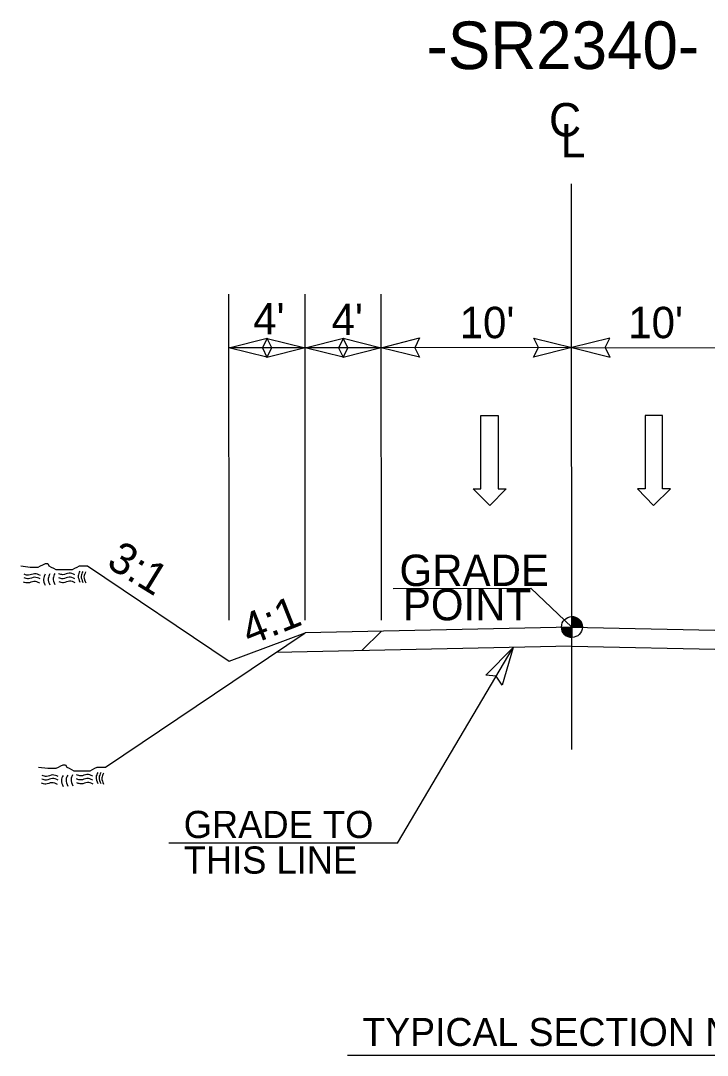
# Model space of a CAD drawing. Extents: x 2241081 to 2251104, y 658534 to 663427.
# Drawn here: x 2241729 to 2241909.2, y 660188.5 to 660460.2 of the extents above; entities that cross this region are included whole.
import ezdxf

# ---------------------------------------------------------------- set-up
doc = ezdxf.new("R2010")
doc.units = 0
for name, color, linetype in [('Old_Level_1', 7, 'Continuous'), ('Old_Level_11', 7, 'Continuous'), ('Old_Level_2', 7, 'Continuous'), ('Old_Level_3', 7, 'Continuous'), ('Prop Dimension Text', 7, 'Continuous'), ('Prop Lane Arrow CELL', 7, 'Continuous'), ('Typical Grade Point Symbol CELL', 7, 'Continuous'), ('Typical Hinge Slope Interstate CELL', 7, 'Continuous'), ('Typical Terminator CELL', 7, 'Continuous'), ('Typical Text Centerline CELL', 7, 'Continuous'), ('Typical Text Grade Point CELL', 7, 'Continuous'), ('Typical Text Label CELL', 7, 'Continuous')]:
    doc.layers.add(name, color=color, linetype=linetype)

# ---------------------------------------------------------------- blocks, each defined once
blk = doc.blocks.new('TERMINATOR')
at = {"layer": 'Typical Terminator CELL'}
blk.add_lwpolyline([(-0.4687, 0.0807), (0, 0), (-0.4713, -0.0833), (-0.4114, 0)], close=True, dxfattribs=at)

msp = doc.modelspace()

# ---------------------------------------------------------------- linework, layer by layer
at = {"layer": 'Old_Level_1'}
for p, q in [((2241746.53, 660316.99), (2241783.69, 660291.99)), ((2241751.23, 660264.14), (2241803.68, 660299.45)), ((2241783.69, 660291.99), (2241803.68, 660299.45))]:
    msp.add_line(p, q, dxfattribs=at)
for points in [[(2241728.97, 660316.99), (2241731.43, 660316.69), (2241732.05, 660316.69), (2241732.98, 660316.69), (2241733.59, 660316.69), (2241734.21, 660316.99), (2241734.82, 660317.3), (2241735.44, 660317.61), (2241736.06, 660317.61), (2241736.37, 660316.99), (2241736.98, 660316.69), (2241737.6, 660316.38), (2241738.21, 660316.07), (2241738.83, 660316.07), (2241739.45, 660316.07), (2241740.06, 660316.07), (2241740.68, 660316.07), (2241741.29, 660316.07), (2241741.91, 660316.07), (2241742.53, 660316.07), (2241743.14, 660316.38), (2241743.76, 660316.69), (2241744.37, 660316.99), (2241745.3, 660316.99), (2241745.92, 660316.99), (2241746.53, 660316.99)], [(2241733.67, 660264.14), (2241736.13, 660263.84), (2241736.75, 660263.84), (2241737.67, 660263.84), (2241738.29, 660263.84), (2241738.9, 660264.14), (2241739.52, 660264.45), (2241740.14, 660264.76), (2241740.75, 660264.76), (2241741.06, 660264.14), (2241741.68, 660263.84), (2241742.3, 660263.53), (2241742.91, 660263.22), (2241743.53, 660263.22), (2241744.14, 660263.22), (2241744.76, 660263.22), (2241745.38, 660263.22), (2241745.99, 660263.22), (2241746.61, 660263.22), (2241747.22, 660263.22), (2241747.84, 660263.53), (2241748.46, 660263.84), (2241749.07, 660264.14), (2241750, 660264.14), (2241750.61, 660264.14), (2241751.23, 660264.14)]]:
    msp.add_lwpolyline(points, dxfattribs=at)
at = {"layer": 'Old_Level_11'}
msp.add_line((2241827.86, 660244.22), (2241858.28, 660295.6), dxfattribs=at)
at = {"layer": 'Old_Level_2'}
for p, q in [((2241873.68, 660300.94), (2241803.68, 660299.45)), ((2241873.59, 660300.94), (2241943.59, 660299.45)), ((2241823.68, 660299.87), (2241818.57, 660294.76)), ((2241873.58, 660295.94), (2241796.01, 660294.28)), ((2241873.69, 660295.94), (2241951.27, 660294.28))]:
    msp.add_line(p, q, dxfattribs=at)
for points in [[(2241734.1, 660313.57), (2241732.6, 660314.01), (2241731.01, 660313.6), (2241729.86, 660313.85)], [(2241734.1, 660313.57), (2241732.6, 660314.01), (2241731.01, 660313.6), (2241729.86, 660313.85)], [(2241734.14, 660314.52), (2241732.63, 660314.95), (2241731.05, 660314.54), (2241729.9, 660314.79)], [(2241734.14, 660314.52), (2241732.63, 660314.95), (2241731.05, 660314.54), (2241729.9, 660314.79)], [(2241735.39, 660314.8), (2241734.96, 660313.56), (2241735.42, 660311.92)], [(2241735.39, 660314.8), (2241734.96, 660313.56), (2241735.42, 660311.92)], [(2241736.6, 660314.91), (2241736.18, 660313.67), (2241736.63, 660312.02)], [(2241736.6, 660314.91), (2241736.18, 660313.67), (2241736.63, 660312.02)], [(2241737.91, 660315.01), (2241737.49, 660313.77), (2241737.94, 660312.13)], [(2241737.91, 660315.01), (2241737.49, 660313.77), (2241737.94, 660312.13)], [(2241743.17, 660314.66), (2241741.67, 660315.09), (2241740.07, 660314.69), (2241738.93, 660314.94)], [(2241743.17, 660314.66), (2241741.67, 660315.09), (2241740.07, 660314.69), (2241738.93, 660314.94)], [(2241743.18, 660313.61), (2241741.67, 660314.04), (2241740.09, 660313.63), (2241738.94, 660313.89)], [(2241743.18, 660313.61), (2241741.67, 660314.04), (2241740.09, 660313.63), (2241738.94, 660313.89)], [(2241744.5, 660315.63), (2241744.07, 660314.38), (2241744.53, 660312.74)], [(2241744.5, 660315.63), (2241744.07, 660314.38), (2241744.53, 660312.74)], [(2241745.28, 660315.55), (2241744.86, 660314.3), (2241745.32, 660312.65)], [(2241745.28, 660315.55), (2241744.86, 660314.3), (2241745.32, 660312.65)], [(2241746.01, 660315.4), (2241745.58, 660314.16), (2241746.04, 660312.52)], [(2241746.01, 660315.4), (2241745.58, 660314.16), (2241746.04, 660312.52)], [(2241733.95, 660312.48), (2241732.45, 660312.91), (2241730.85, 660312.51), (2241729.71, 660312.76)], [(2241743.3, 660312.56), (2241741.79, 660312.98), (2241740.2, 660312.58), (2241739.05, 660312.84)], [(2241743.3, 660312.56), (2241741.79, 660312.98), (2241740.2, 660312.58), (2241739.05, 660312.84)], [(2241738.84, 660261.67), (2241737.33, 660262.1), (2241735.75, 660261.69), (2241734.6, 660261.95)], [(2241738.84, 660261.67), (2241737.33, 660262.1), (2241735.75, 660261.69), (2241734.6, 660261.95)], [(2241740.08, 660261.96), (2241739.66, 660260.71), (2241740.12, 660259.07)], [(2241740.08, 660261.96), (2241739.66, 660260.71), (2241740.12, 660259.07)], [(2241741.3, 660262.07), (2241740.87, 660260.82), (2241741.33, 660259.17)], [(2241741.3, 660262.07), (2241740.87, 660260.82), (2241741.33, 660259.17)], [(2241742.61, 660262.17), (2241742.19, 660260.93), (2241742.64, 660259.28)], [(2241742.61, 660262.17), (2241742.19, 660260.93), (2241742.64, 660259.28)], [(2241747.87, 660261.81), (2241746.37, 660262.24), (2241744.77, 660261.84), (2241743.63, 660262.1)], [(2241747.87, 660261.81), (2241746.37, 660262.24), (2241744.77, 660261.84), (2241743.63, 660262.1)], [(2241749.2, 660262.78), (2241748.77, 660261.54), (2241749.23, 660259.89)], [(2241749.2, 660262.78), (2241748.77, 660261.54), (2241749.23, 660259.89)], [(2241749.97, 660262.7), (2241749.56, 660261.45), (2241750.01, 660259.81)], [(2241749.97, 660262.7), (2241749.56, 660261.45), (2241750.01, 660259.81)], [(2241750.71, 660262.56), (2241750.28, 660261.32), (2241750.74, 660259.67)], [(2241750.71, 660262.56), (2241750.28, 660261.32), (2241750.74, 660259.67)], [(2241738.65, 660259.63), (2241737.14, 660260.06), (2241735.55, 660259.66), (2241734.41, 660259.92)], [(2241738.8, 660260.72), (2241737.29, 660261.16), (2241735.71, 660260.75), (2241734.56, 660261.01)], [(2241738.8, 660260.72), (2241737.29, 660261.16), (2241735.71, 660260.75), (2241734.56, 660261.01)], [(2241747.88, 660260.77), (2241746.37, 660261.19), (2241744.79, 660260.78), (2241743.64, 660261.04)], [(2241747.88, 660260.77), (2241746.37, 660261.19), (2241744.79, 660260.78), (2241743.64, 660261.04)], [(2241747.99, 660259.71), (2241746.49, 660260.13), (2241744.89, 660259.74), (2241743.75, 660259.99)], [(2241747.99, 660259.71), (2241746.49, 660260.13), (2241744.89, 660259.74), (2241743.75, 660259.99)]]:
    msp.add_spline(points, degree=3, dxfattribs=at)
at = {"layer": 'Prop Dimension Text'}
for p, q in [((2241783.68, 660302.76), (2241783.63, 660388.35)), ((2241803.68, 660302.77), (2241803.63, 660388.36)), ((2241823.68, 660302.79), (2241823.63, 660388.38)), ((2241803.64, 660374.29), (2241783.64, 660374.28)), ((2241823.64, 660374.31), (2241803.64, 660374.29)), ((2241873.64, 660374.34), (2241823.64, 660374.31)), ((2241873.64, 660374.34), (2241923.64, 660374.31)), ((2241827.86, 660244.22), (2241767.86, 660244.18))]:
    msp.add_line(p, q, dxfattribs=at)
at = {"layer": 'Prop Lane Arrow CELL'}
for p, q in [((2241849.78, 660356.49), (2241854.33, 660356.5)), ((2241849.8, 660337.2), (2241849.78, 660356.49)), ((2241854.33, 660356.5), (2241854.34, 660337.2)), ((2241892.94, 660356.5), (2241892.93, 660337.2)), ((2241897.49, 660356.49), (2241892.94, 660356.5)), ((2241897.48, 660337.2), (2241897.49, 660356.49)), ((2241852.14, 660332.86), (2241847.73, 660337.2)), ((2241847.73, 660337.2), (2241849.8, 660337.2)), ((2241856.41, 660337.2), (2241852.14, 660332.86)), ((2241854.34, 660337.2), (2241856.41, 660337.2)), ((2241892.93, 660337.2), (2241890.86, 660337.2)), ((2241890.86, 660337.2), (2241895.13, 660332.86)), ((2241895.13, 660332.86), (2241899.55, 660337.2)), ((2241899.55, 660337.2), (2241897.48, 660337.2))]:
    msp.add_line(p, q, dxfattribs=at)
at = {"layer": 'Typical Grade Point Symbol CELL'}
for p, q in [((2241873.68, 660300.94), (2241862.93, 660311.11)), ((2241873.68, 660300.94), (2241873.68, 660303.69)), ((2241870.94, 660300.94), (2241873.68, 660300.94)), ((2241876.42, 660300.95), (2241873.68, 660300.94)), ((2241873.68, 660298.2), (2241873.68, 660300.94)), ((2241873.68, 660300.94), (2241873.68, 660298.2))]:
    msp.add_line(p, q, dxfattribs=at)
for points in [[(2241873.71, 660303.69), (2241873.71, 660303.69), (2241873.71, 660300.94)], [(2241873.76, 660303.69), (2241873.76, 660300.94)], [(2241873.82, 660303.68), (2241873.82, 660300.94)], [(2241873.87, 660303.68), (2241873.87, 660300.94)], [(2241873.92, 660303.67), (2241873.93, 660300.94)], [(2241873.98, 660303.67), (2241873.98, 660300.94)], [(2241874.03, 660303.66), (2241874.04, 660300.94)], [(2241874.09, 660303.66), (2241874.09, 660300.94)], [(2241874.14, 660303.65), (2241874.15, 660300.94)], [(2241874.2, 660303.64), (2241874.2, 660300.94)], [(2241874.25, 660303.63), (2241874.26, 660300.94)], [(2241874.31, 660303.61), (2241874.31, 660300.94)], [(2241874.36, 660303.6), (2241874.37, 660300.94)], [(2241874.42, 660303.58), (2241874.42, 660300.94)], [(2241874.47, 660303.57), (2241874.47, 660300.94)], [(2241874.53, 660303.55), (2241874.53, 660300.94)], [(2241874.58, 660303.53), (2241874.58, 660300.94)], [(2241874.64, 660303.52), (2241874.64, 660300.94)], [(2241874.69, 660303.49), (2241874.69, 660300.94)], [(2241874.75, 660303.47), (2241874.75, 660300.94)], [(2241874.8, 660303.44), (2241874.8, 660300.94)], [(2241874.86, 660303.42), (2241874.86, 660300.94)], [(2241874.91, 660303.39), (2241874.91, 660300.94)], [(2241874.97, 660303.36), (2241874.97, 660300.94)], [(2241875.02, 660303.33), (2241875.02, 660300.94)], [(2241875.08, 660303.3), (2241875.08, 660300.94)], [(2241875.13, 660303.27), (2241875.13, 660300.94)], [(2241875.19, 660303.24), (2241875.19, 660300.94)], [(2241875.24, 660303.2), (2241875.24, 660300.94)], [(2241875.3, 660303.16), (2241875.3, 660300.94)], [(2241875.35, 660303.12), (2241875.35, 660300.94)], [(2241875.41, 660303.08), (2241875.41, 660300.94)], [(2241875.46, 660303.03), (2241875.46, 660300.94)], [(2241875.52, 660302.98), (2241875.52, 660300.94)], [(2241875.57, 660302.93), (2241875.57, 660300.94)], [(2241875.63, 660302.88), (2241875.63, 660300.94)], [(2241875.68, 660302.82), (2241875.68, 660300.94)], [(2241875.73, 660302.76), (2241875.74, 660300.94)], [(2241875.79, 660302.69), (2241875.79, 660300.94)], [(2241870.95, 660300.94), (2241870.95, 660300.64)], [(2241871.01, 660300.94), (2241871.01, 660300.32)], [(2241871.06, 660300.94), (2241871.06, 660300.13)], [(2241871.12, 660300.94), (2241871.12, 660299.96)], [(2241871.17, 660300.94), (2241871.17, 660299.83)], [(2241871.23, 660300.94), (2241871.23, 660299.72)], [(2241871.28, 660300.94), (2241871.28, 660299.61)], [(2241871.34, 660300.94), (2241871.34, 660299.52)], [(2241871.39, 660300.94), (2241871.39, 660299.43)], [(2241871.45, 660300.94), (2241871.45, 660299.35)], [(2241871.5, 660300.94), (2241871.5, 660299.28)], [(2241871.56, 660300.94), (2241871.56, 660299.21)], [(2241871.61, 660300.94), (2241871.61, 660299.15)], [(2241871.67, 660300.94), (2241871.67, 660299.08)], [(2241871.72, 660300.94), (2241871.72, 660299.02)], [(2241871.78, 660300.94), (2241871.78, 660298.97)], [(2241871.83, 660300.94), (2241871.83, 660298.92)], [(2241871.89, 660300.94), (2241871.89, 660298.87)], [(2241871.94, 660300.94), (2241871.94, 660298.82)], [(2241872, 660300.94), (2241872, 660298.78)], [(2241872.05, 660300.94), (2241872.05, 660298.74)], [(2241872.1, 660300.94), (2241872.11, 660298.7)], [(2241872.16, 660300.94), (2241872.16, 660298.66)], [(2241872.21, 660300.94), (2241872.22, 660298.63)], [(2241872.27, 660300.94), (2241872.27, 660298.59)], [(2241872.32, 660300.94), (2241872.33, 660298.56)], [(2241872.38, 660300.94), (2241872.38, 660298.53)], [(2241872.43, 660300.94), (2241872.44, 660298.5)], [(2241872.49, 660300.94), (2241872.49, 660298.48)], [(2241872.54, 660300.94), (2241872.55, 660298.45)], [(2241872.6, 660300.94), (2241872.6, 660298.43)], [(2241872.65, 660300.94), (2241872.65, 660298.4)], [(2241872.71, 660300.94), (2241872.71, 660298.38)], [(2241872.76, 660300.94), (2241872.76, 660298.36)], [(2241872.82, 660300.94), (2241872.82, 660298.34)], [(2241872.87, 660300.94), (2241872.87, 660298.32)], [(2241872.93, 660300.94), (2241872.93, 660298.31)], [(2241872.98, 660300.94), (2241872.98, 660298.29)], [(2241873.04, 660300.94), (2241873.04, 660298.28)], [(2241873.09, 660300.94), (2241873.09, 660298.27)], [(2241873.15, 660300.94), (2241873.15, 660298.26)], [(2241873.2, 660300.94), (2241873.2, 660298.24)], [(2241873.26, 660300.94), (2241873.26, 660298.24)], [(2241873.31, 660300.94), (2241873.31, 660298.23)], [(2241873.37, 660300.94), (2241873.37, 660298.22)], [(2241873.42, 660300.94), (2241873.42, 660298.21)], [(2241873.48, 660300.94), (2241873.48, 660298.21)], [(2241873.53, 660300.94), (2241873.53, 660298.21)], [(2241873.59, 660300.94), (2241873.59, 660298.2)], [(2241873.64, 660300.94), (2241873.64, 660298.2), (2241873.64, 660298.2)], [(2241875.84, 660302.63), (2241875.85, 660300.94)], [(2241875.9, 660302.55), (2241875.9, 660300.95)], [(2241875.95, 660302.47), (2241875.96, 660300.95)], [(2241876.01, 660302.39), (2241876.01, 660300.95)], [(2241876.06, 660302.3), (2241876.06, 660300.95)], [(2241876.12, 660302.2), (2241876.12, 660300.95)], [(2241876.16, 660302.08), (2241876.16, 660300.94)], [(2241876.21, 660301.96), (2241876.22, 660300.94)], [(2241876.27, 660301.8), (2241876.27, 660300.94)], [(2241876.32, 660301.61), (2241876.33, 660300.94)], [(2241876.38, 660301.33), (2241876.38, 660300.94)]]:
    msp.add_lwpolyline(points, dxfattribs=at)
msp.add_circle((2241873.68, 660300.94), 2.74, dxfattribs=at)
for start, end in [(0.0254, 90.0254), (180.0254, 270.0254)]:
    msp.add_arc((2241873.68, 660300.94), 2.74, start, end, dxfattribs=at)
at = {"layer": 'Typical Text Centerline CELL'}
msp.add_line((2241873.7, 660268.77), (2241873.61, 660417.32), dxfattribs=at)
at = {"layer": 'Typical Text Grade Point CELL'}
msp.add_line((2241826.8, 660311.09), (2241862.93, 660311.11), dxfattribs=at)
at = {"layer": 'Typical Text Label CELL'}
msp.add_line((2241814.73, 660188.46), (2241947.59, 660188.46), dxfattribs=at)

# ---------------------------------------------------------------- block references
at = {"layer": 'Typical Terminator CELL'}
for p, xscale, yscale, rotation in [((2241783.64, 660374.28), 21.314641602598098, 30.59316138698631, -179.96511250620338), ((2241803.64, 660374.29), 21.314641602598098, 30.59316138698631, 0.03488749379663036), ((2241803.64, 660374.29), 21.314641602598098, 30.59316138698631, -179.96511250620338), ((2241823.64, 660374.31), 21.314641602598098, 30.59316138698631, 0.03488749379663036), ((2241823.64, 660374.31), 21.314641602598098, 30.59316138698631, -179.96511250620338), ((2241873.64, 660374.34), 21.314641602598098, 30.59316138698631, 0.03488749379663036), ((2241873.64, 660374.34), 21.314641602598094, -30.59316138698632, 179.96498243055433), ((2241858.28, 660295.6), 21.314641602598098, 30.593161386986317, 59.367986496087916)]:
    msp.add_blockref('TERMINATOR', p, dxfattribs=dict(at, xscale=xscale, yscale=yscale, rotation=rotation))

# ---------------------------------------------------------------- texts
at = {"layer": 'Old_Level_3'}
for s, p in [('GRADE TO', (2241771.76, 660245.53)), ('THIS LINE', (2241771.76, 660236.18))]:
    msp.add_text(s, height=7.131, rotation=359.9999, dxfattribs=at).set_placement(p)
at = {"layer": 'Prop Dimension Text'}
for s, height, rotation, p in [('-SR2340-', 12.5, 0.0349, (2241835.54, 660447.47)), ("4'", 8.25, 0.0349, (2241790.02, 660377.78)), ("4'", 8.25, 0.0349, (2241810.59, 660377.61)), ("10'", 8.25, 0.0349, (2241844.21, 660376.8)), ("10'", 8.25, 359.965, (2241888.47, 660376.81))]:
    msp.add_text(s, height=height, rotation=rotation, dxfattribs=at).set_placement(p)
at = {"layer": 'Typical Hinge Slope Interstate CELL'}
for s, rotation, p in [('3:1', 328.4414, (2241751.16, 660316.95)), ('4:1', 21.6462, (2241789.02, 660296.02))]:
    msp.add_text(s, height=8.25, rotation=rotation, dxfattribs=at).set_placement(p)
at = {"layer": 'Typical Text Centerline CELL'}
for s, rotation, p in [('C', 0.0349, (2241867.67, 660429.8)), ('L', 359.9818, (2241870.7, 660424.3))]:
    msp.add_text(s, height=8.76, rotation=rotation, dxfattribs=at).set_placement(p)
at = {"layer": 'Typical Text Grade Point CELL'}
for s, p in [('GRADE', (2241828.42, 660311.71)), ('POINT', (2241829.3, 660302.71))]:
    msp.add_text(s, height=8.25, rotation=0.0349, dxfattribs=at).set_placement(p)
at = {"layer": 'Typical Text Label CELL'}
msp.add_text('TYPICAL SECTION NO.  ', height=7.3404, dxfattribs=at).set_placement((2241818.67, 660190.92))

doc.saveas('drawing.dxf')
